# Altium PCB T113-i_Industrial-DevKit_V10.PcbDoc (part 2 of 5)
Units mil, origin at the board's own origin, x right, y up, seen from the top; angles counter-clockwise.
Board outline 4212.61 x 3188.98 mil, 4 copper layers (Top Layer, GND, PWR, Bottom Layer); 249 components, 236 nets, 911 pads, 571 vias.
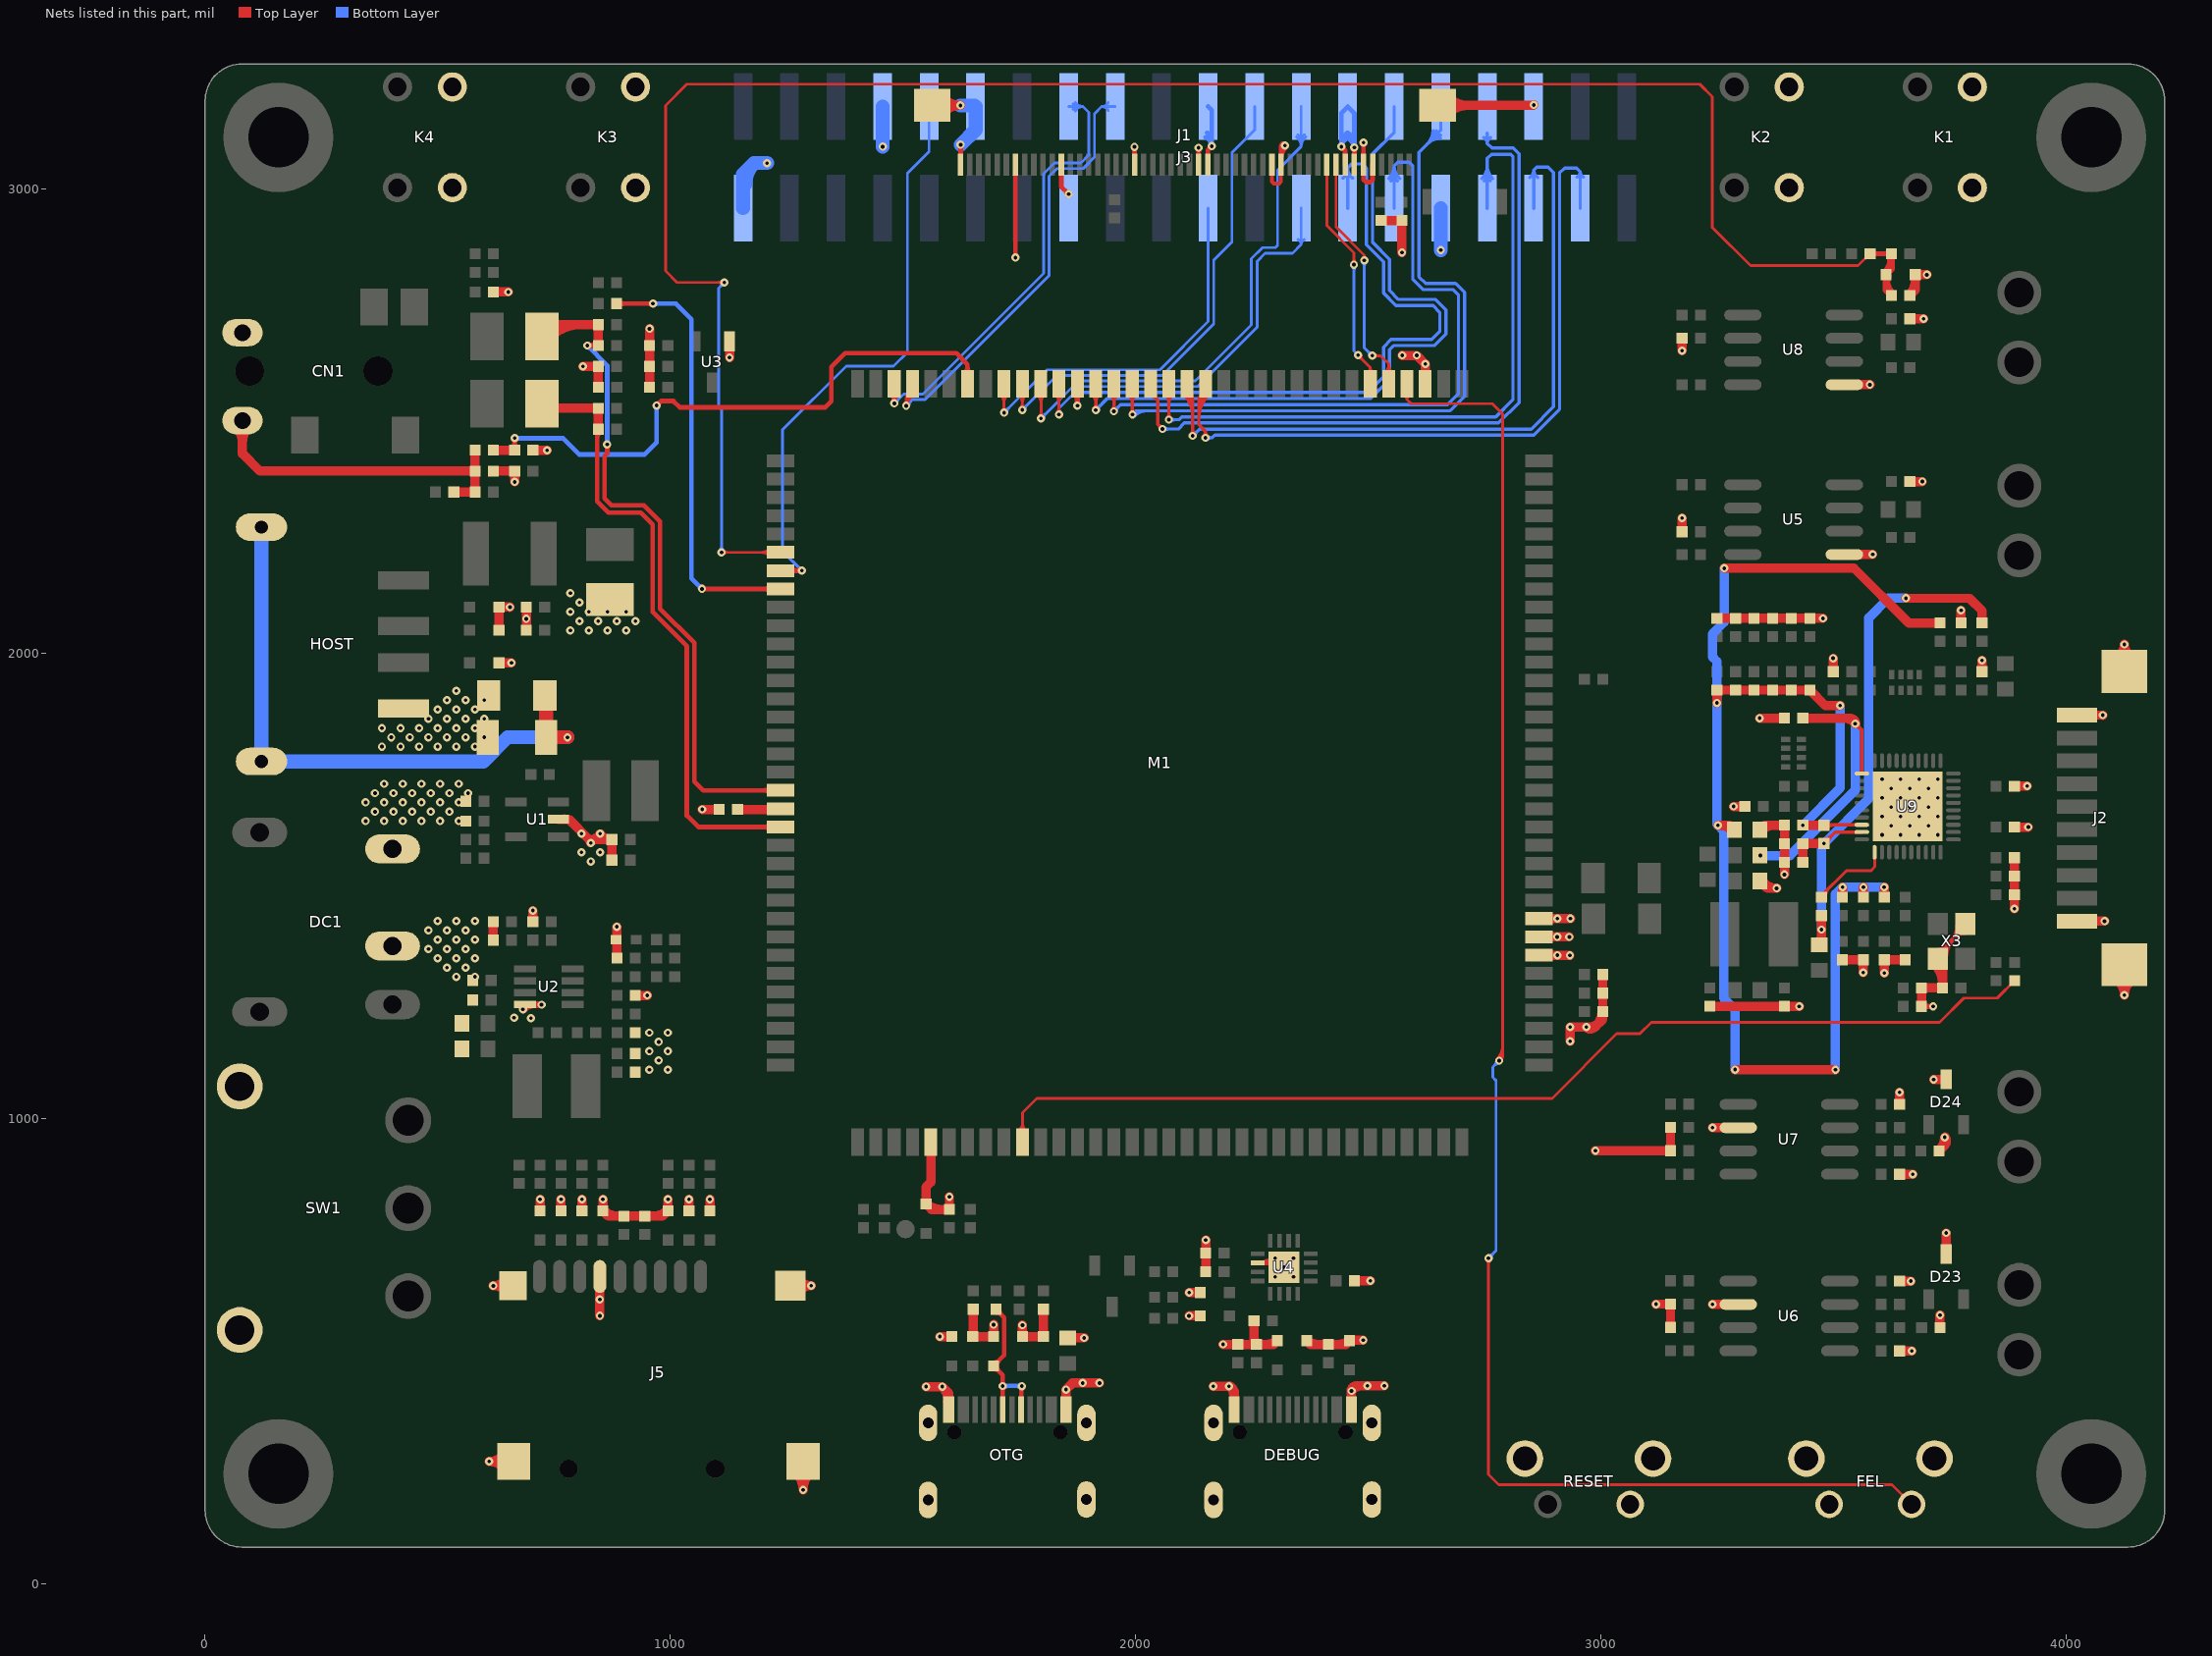
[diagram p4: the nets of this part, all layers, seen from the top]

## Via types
v1: diameter 17.72, hole 7.87, Top Layer to Bottom Layer, tented both sides, 571 vias

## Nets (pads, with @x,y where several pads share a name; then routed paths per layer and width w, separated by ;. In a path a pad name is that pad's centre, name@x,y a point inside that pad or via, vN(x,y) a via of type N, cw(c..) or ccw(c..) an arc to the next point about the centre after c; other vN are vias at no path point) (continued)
DP_P0: D17.2 OTG.A6 OTG.B6 R38.1 | length 487.7
  Top Layer w9.53: D17.2@1695,461.46 cw(c1695,444.45) 1707.03,456.48 cw(c1719.06,468.5) 1702.05,468.5 cw(c1719.06,468.5) 1707.03,480.53 cw(c1695,492.56) D17.2@1695,475.55 ; R38.1@1700,583.27 cw(c1700,566.26) 1712.03,578.29 cw(c1724.06,590.32) R38.1@1707.05,590.32 ; R38.1@1700,590.32 1718,572.32 1718,491.5 D17.2@1695,468.5 1714.72,448.78 v1(1714.72,425.05) OTG.A6@1714.72,374.13 ; v1@1711.83,422.16 cw(c1704.84,415.17) 1714.72,415.17 cw(c1724.61,415.17) v1@1717.62,422.16 ; v1@1711.83,427.95 ccw(c1704.84,434.93) 1714.72,434.93 ccw(c1724.61,434.93) v1@1717.62,427.95 ; OTG.B6@1754.09,374.13 1754.09,423.32 v1(1755.62,424.84) ; 1754.09,411.29 cw(c1769.17,411.29) v1@1758.51,421.95
  Bottom Layer w9.53: v1(1714.72,425.05) 1755.41,425.05 v1(1755.62,424.84) ; v1@1717.62,422.16 cw(c1724.61,415.17) 1724.61,425.05 cw(c1724.61,434.93) v1@1717.62,427.95 ; 1745.23,425.05 cw(c1745.23,414.45) v1@1752.72,421.95 ; 1746.24,425.05 ccw(c1746.24,434.22) v1@1752.72,427.74
DVDD10: C77.1 R94.1 U9.21 | length 701.7
  Top Layer w8: v1@3547.3,1844.51 cw(c3547.3,1832.78) 3555.59,1841.08 cw(c3563.88,1849.37) v1@3552.16,1849.37 ; v1(3547.3,1849.37) 3561.6,1835.07 U9.21@3561.6,1742.16
  Top Layer w20: C77.1@3434.68,1861.26 3435.01,1860.94 3535.73,1860.94 ; 3522.12,1860.94 cw(c3522.12,1824.2) v1@3548.11,1850.18 ; v1(3547.3,1849.37) 3535.73,1860.94 ; v1@3548.43,1849.49 ccw(c3535.73,1848.17) 3535.73,1860.94
  Bottom Layer w20: v1(3343.64,1565.87) 3407.09,1565.87 3547.3,1706.07 v1(3547.3,1849.37)
DVDD33: C64.1 C67.1 R77.1 R84.2 R85.2 R130.2 U9.29 | length 1357.6
  Top Layer w8: R130.2@3477.09,1592.75 cw(c3490.24,1587.45) R130.2@3486.57,1601.15 ; v1(3480,1591.57) 3504.59,1616.16 U9.29@3561.6,1616.16 ; R130.2@3480,1596.43 ccw(c3480,1608.16) 3488.29,1599.87 ccw(c3496.59,1591.57) R130.2@3484.86,1591.57 ; R130.2@3480,1599.39 ccw(c3480,1618.24) 3493.33,1604.91 ccw(c3506.67,1591.57) R130.2@3487.81,1591.57 ; R130.2@3481.17,1588.66 ccw(c3475.87,1601.81) R130.2@3489.57,1598.14
  Top Layer w20: C67.1@3434.68,1551.26 C64.1@3434.68,1591.26 3435,1591.57 v1(3480,1591.57) ; R77.1@3467.9,1377.88 ccw(c3450.77,1395.01) 3475,1395.01 ; R77.1@3470,1373.82 3475,1378.82 R85.2@3475,1436.57 ; v1(3656.12,2119.13) 3656.35,2118.9 3793.43,2118.9 3820,2092.32 R84.2@3820,2065.94
  Bottom Layer w20: v1(3475.02,1406.53) 3475.02,1586.59 v1(3480,1591.57) 3576.39,1687.97 3576.39,2076.97 3618.55,2119.13 v1(3656.12,2119.13) ; 3475.02,1582.31 cw(c3489.27,1582.31) v1@3479.19,1592.38
DVDDRG: C63.1 C66.1 R87.2 R90.1 R91.1 R92.1 R101.1 R102.1 R103.1 R104.1 R105.1 R106.1 R130.1 U9.28 | length 3216.2
  Top Layer w8: R130.1@3480,1630.94 3480.92,1631.86 U9.28@3561.6,1631.86 ; R130.1@3485.52,1625.42 cw(c3501.07,1609.87) 3501.07,1631.86 ; R130.1@3485.52,1636.47 ccw(c3496.64,1647.59) 3496.64,1631.86
  Top Layer w20: v1(3250.16,1893.93) 3250,1894.09 R105.1@3250,1921.57 R104.1@3290,1921.57 R90.1@3330,1921.57 R91.1@3370,1921.57 R92.1@3410,1921.57 R106.1@3450,1921.57 3483.14,1888.43 v1(3515.22,1888.43) ; v1(3252.23,1630.7) 3278,1630.7 C66.1@3287.44,1621.26 ; v1@3255.53,1630.7 cw(c3255.53,1591.31) C66.1@3283.38,1619.16 ; v1@3265.74,2183.73 3544.55,2183.73 3662.34,2065.94 R87.2@3730,2065.94 ; v1(3289,1105.62) v1@3504.92,1105.62 ; v1(3435,1630.94) R130.1@3480,1630.94 ; R103.1@3520,1475.94 3520,1497.78 v1(3520.28,1498.06) ; R102.1@3565,1475.94 3565,1497.91 v1(3565.15,1498.06) ; v1(3609.56,1498.06) 3609.56,1476.38 R101.1@3610,1475.94
  Bottom Layer w20: v1(3265.74,2183.5) 3265.74,2067.58 3241,2042.84 3241,1992.36 3250.16,1983.2 v1(3250.16,1893.93) 3250.16,1632.76 v1(3252.23,1630.7) 3264.37,1618.56 3264.37,1259.11 3288.65,1234.83 3288.65,1105.96 v1(3289,1105.62) ; v1(3435,1630.94) 3515.45,1711.4 3515.45,1888.2 v1(3515.22,1888.43) ; v1(3504.92,1105.45) 3504.92,1482.7 v1(3520.28,1498.06) v1(3565.15,1498.06) v1(3609.56,1498.06)
EPHY_CLK_25M: M1.44 R80.2 | length 2354.2
  Top Layer w6: M1.44@1749.27,973.37 ccw(c1730.87,991.77) 1756.89,991.77 ccw(c1782.91,991.77) M1.44@1764.51,973.37 ; M1.44@1756.89,950 1756.89,1012.56 1788.12,1043.79 2895.67,1043.79 3034.54,1182.66 3084.25,1182.66 3108.84,1207.25 3728.9,1207.25 3780.99,1259.34 3852.77,1259.34 R80.2@3890,1296.57
FEL: FEL.1 M1.106 | length 3640.2
  Top Layer w6: M1.106@2578.51,2554.7 cw(c2573.8,2546.04) 2583.66,2546.04 ; M1.106@2583.66,2579.92 2583.66,2546.04 ; M1.106@2588.81,2554.7 ccw(c2593.52,2546.04) 2583.66,2546.04 ; v1@2754.85,695.75 cw(c2745.19,686.09) 2758.85,686.09 ; 2758.85,685.41 cw(c2773.47,685.41) v1@2763.13,695.75 ; v1(2758.99,699.89) 2758.85,699.75 2758.85,235.23 2781,213.07 3626.29,213.07 FEL.1@3668.58,170.78 ; v1@2777.76,1128.89 ccw(c2749.5,1157.14) 2789.46,1157.14 ; v1(2781.9,1124.75) 2789.46,1132.31 ; v1@2782,1124.65 ccw(c2763.99,1142.66) 2789.46,1142.66 ; v1@2783.16,1130.47 ccw(c2784.63,1137.13) 2789.46,1132.31 ; v1@2787.62,1126.01 cw(c2794.28,1127.48) 2789.46,1132.31 ; 2583.66,2546.04 2592.48,2537.22 2767.47,2537.22 2789.46,2515.23 2789.46,1132.31
  Bottom Layer w6: v1(2758.99,699.89) 2775.1,716.01 2775.1,1082.16 2768.15,1089.11 2768.15,1111 v1(2781.9,1124.75) ; v1@2758.99,705.75 ccw(c2758.99,719.9) 2768.99,709.9 ccw(c2778.99,699.89) v1@2764.85,699.89 ; v1@2776.04,1124.75 cw(c2761.9,1124.75) 2771.9,1114.75 cw(c2781.9,1104.75) v1@2781.9,1118.89
FMINL: J3.24 M1.133 | length 1170.7
  Top Layer w6: v1@1503.07,2536.91 ccw(c1493.07,2546.91) 1507.22,2546.91 ; v1@1504.29,2537.84 ccw(c1499.73,2545.72) 1508.53,2543.37 ; v1@1505.55,2538.38 ccw(c1503.31,2545.96) 1510.94,2543.91 ccw(c1520.69,2541.3) v1@1512.16,2535.9 ; v1@1507.22,2530.01 cw(c1532.64,2530.01) M1.133@1524.23,2554 ; v1(1507.22,2532.76) 1507.22,2549.58 ; v1@1507.21,2538.46 cw(c1529.68,2538.46) M1.133@1522.25,2559.66 ; 1509.56,2547.23 ccw(c1521.44,2544.04) v1@1511.81,2536.4 ; M1.133@1510.29,2561.28 cw(c1498.74,2558.06) 1507.22,2549.58 ; v1@1511.36,2536.91 cw(c1521.36,2546.91) 1507.21,2546.91 ; M1.133@1519.09,2553.51 ccw(c1517.05,2539.75) 1507.22,2549.58 ; M1.133@1520.27,2565.33 ccw(c1526.71,2546.92) 1507.22,2546.92 ; M1.133@1520.67,2579.92 1520.67,2563.04 1507.22,2549.58
  Bottom Layer w6: v1(1507.22,2532.76) 1520.59,2546.14 1547.63,2546.14 1814.37,2812.88 1814.37,3026.27 1831.15,3043.06 1887.54,3043.06 1911.83,3067.36 1911.83,3160.84 1927.25,3176.26 ; v1@1507.22,2538.62 ccw(c1507.22,2552.77) 1517.22,2542.76 ccw(c1527.22,2532.76) v1@1513.07,2532.76 ; J3.24@1941.38,3167.95 ccw(c1927.25,3160.09) 1927.25,3176.26 ; J3.24@1941.38,3184.56 cw(c1927.25,3192.43) 1927.25,3176.26 ; J3.24@1956.3,3176.26 1927.25,3176.26
FMINR: J3.26 M1.134 | length 1143.8
  Top Layer w6: M1.134@1473.68,2556.55 cw(c1455.62,2538.5) v1@1481.15,2538.5 ; v1@1476.49,2540.95 ccw(c1465.06,2547.56) M1.134@1477.81,2550.97 ; v1@1477.42,2542.17 ccw(c1468.42,2551.17) M1.134@1481.15,2551.17 ; M1.134@1477.61,2551.72 ccw(c1490.92,2555.29) v1@1484.36,2543.17 ; v1@1478.78,2543.18 ccw(c1473.18,2553.54) 1484.55,2550.49 ccw(c1494.68,2547.78) v1@1486.27,2541.52 ; v1@1481.15,2532.12 1481.15,2579.78 M1.134@1481.3,2579.92 ; v1@1481.15,2537.8 cw(c1507.67,2537.8) M1.134@1488.92,2556.55 ; M1.134@1481.15,2553.16 ccw(c1496.7,2553.16) v1@1485.71,2542.17
  Bottom Layer w6: v1(1481.57,2538.02) 1501.68,2558.14 1542.66,2558.14 1802.3,2817.79 1802.3,3031.62 1825.74,3055.06 1882.57,3055.06 1899.83,3072.33 1899.83,3163.73 1887.31,3176.26 ; v1@1481.57,2543.88 ccw(c1481.57,2558.03) 1491.57,2548.02 ccw(c1501.57,2538.02) v1@1487.42,2538.02 ; J3.26@1856.3,3176.26 1887.31,3176.26 ; J3.26@1865.66,3170.34 cw(c1876.41,3163.54) 1876.41,3176.26 cw(c1876.41,3188.98) J3.26@1865.66,3182.18 ; J3.26@1870.73,3167.13 cw(c1887.31,3156.65) 1887.31,3176.26 ; J3.26@1870.73,3185.39 ccw(c1887.31,3195.87) 1887.31,3176.26
GND: C1.1 C2.1 C3.1 C4.2 C5.2 C7.2 C8.2 C9.2 C10.1 C11.1 C12.2 C13.2 C15.2 C16.2 C18.2 C19.2 C20.2 C21.1 C23.2 C24.2 C25.2 C30.1 C33.1 C34.2 C35.2 C36.2 C37.2 C38.1 C39.1 C40.1 C41.2 C42.1 C43.2 C44.1 C45.2 C46.2 C47.2 C48.2 C49.1 C50.1 C51.1 C52.2 C53.2 C54.1 C55.1 C56.1 C57.1 C58.2 C59.1 C60.2 C61.2 C62.2 C63.2 C64.2 C65.2 C66.2 C67.2 C68.2 C69.2 C70.2 C71.2 C72.2 C73.2 C74.2 C75.2 C76.2 C77.2 CN1.2 D2.1 D3.1 D4.1 D5.1 D6.1 D7.1 D8.1 D9.1 D10.1 D11.1 D12.1 D13.2 D14.2 D15.1 D16.1 D17.1 D18.1 D19.1 D20.1 D21.1 D22.1 D23.3 D24.3 D25.1 DC1.2 DC1.3 DEBUG.A1B12 DEBUG.B1A12 DEBUG.SHELL FEL.2 FEL.3 FEL.4 HOST.4 J1.5 J1.6 J1.7 J1.8 J1.15 J1.16 J1.23 J1.24 J1.31 J1.39 J1.44 J1.50 J1.51 J1.52 J2.1 J2.10 J2.11 J2.12 J3.6 J3.9 J3.14 J3.20 J3.25 J3.30 J3.34 J3.39 J5.6 J5.10 J5.11 J5.12 J5.13 K1.3 K1.4 K2.3 K2.4 K3.3 K3.4 K4.3 K4.4 LED1.2 M1.39 M1.75 M1.76 M1.77 M1.105 OTG.A1B12 OTG.B1A12 OTG.SHELL R2.2 R4.2 R6.2 R10.2 R17.2 R18.2 R22.1 R27.2 R28.2 R40.1 R41.1 R42.1 R49.1 R50.1 R53.2 R62.2 R79.2 R81.2 R82.2 R83.2 R86.2 R95.2 R96.2 R97.2 R98.2 R99.2 R100.2 RESET.1 RESET.3 RESET.4 SW1.4 SW1.5 U1.2 U2.4 U3.1 U4.2 U4.17 U5.5 U6.2 U7.2 U8.5 U9.41 X3.2 X3.4 | length 10123.8
  Top Layer w8: J1.16@2293.3,3051.03 2293.3,3014.92 2297.46,3010.76 2309.39,3010.76 2312.99,3014.36 J1.15@2312.99,3051.03
  Top Layer w10: v1@1621.39,3091.52 cw(c1615.07,3085.19) 1624.01,3085.19 ; J1.50@1624.01,3051.03 1624.01,3094.14 v1(1624.12,3094.25) ; 1624.01,3084.67 cw(c1633.7,3084.67) v1@1626.85,3091.52 ; v1@1739.41,2854.19 ccw(c1732.86,2860.73) 1742.12,2860.73 ; v1@1742.12,2851.47 J1.44@1742.12,3051.03 ; 1742.12,2860.81 ccw(c1751.49,2860.81) v1@1744.87,2854.19 ; J1.39@1840.55,3051.03 1840.55,3003.89 v1(1856.48,2987.96) ; v1@1852.63,2987.96 ccw(c1843.31,2987.96) 1849.9,2994.55 ccw(c1856.48,3001.13) v1@1856.48,2991.82 ; v1@1995.23,3087.01 cw(c1988.45,3080.23) 1998.03,3080.23 ; v1(1997.95,3089.74) 1998.03,3089.66 J1.31@1998.03,3051.03 ; 1998.03,3080.62 cw(c2007.07,3080.62) v1@2000.68,3087.01 ; v1@2133.04,3085.12 cw(c2126.32,3078.4) 2135.82,3078.4 ; v1(2135.77,3087.85) 2135.82,3087.79 J1.24@2135.82,3051.03 ; 2135.82,3078.67 cw(c2144.95,3078.67) v1@2138.5,3085.12 ; J1.23@2155.51,3051.03 2155.51,3082.71 v1(2163.85,3091.05) ; v1@2159.99,3091.05 cw(c2150.68,3091.05) 2157.27,3084.46 cw(c2163.85,3077.88) v1@2163.85,3087.19 ; U4.2@2262.35,690.1 2309.63,690.1 v1(2319.43,680.3) ; U4.2@2266.78,690.1 ccw(c2266.78,733.22) U4.17@2297.27,702.73 ; U4.17@2290.92,690.1 ccw(c2290.92,709.08) U4.17@2304.34,695.66 ; J1.15@2312.99,3051.03 2312.99,3084.27 v1(2321.08,3092.36) ; J1.15@2312.99,3063.52 cw(c2349.92,3063.52) v1@2323.81,3089.63 ; 2312.99,3087.67 cw(c2325.78,3087.67) v1@2316.74,3096.7 ; U4.17@2315.57,680.3 ccw(c2306.26,680.3) 2312.85,686.89 ccw(c2319.43,693.47) U4.17@2319.43,684.16 ; v1@2317.22,3092.36 cw(c2307.91,3092.36) 2314.49,3085.77 cw(c2321.08,3079.19) v1@2321.08,3088.5 ; v1@2442.66,3086.24 cw(c2442.66,3076.93) 2449.25,3083.51 cw(c2455.84,3090.1) v1@2446.52,3090.1 ; v1(2442.66,3090.1) 2450.78,3081.98 J1.8@2450.78,3051.03 ; v1@2467.77,3085.35 cw(c2461.24,3078.82) 2470.47,3078.82 ; J1.7@2470.47,3051.03 v1@2470.47,3088.05 ; 2470.47,3078.7 cw(c2479.87,3078.7) v1@2473.23,3085.35 ; v1@2487.45,3096.02 cw(c2480.92,3089.49) 2490.15,3089.49 ; 2490.15,3089.38 cw(c2499.55,3089.38) v1@2492.91,3096.02 ; v1@2490.15,3098.73 J1.6@2490.15,3051.03 2490.15,3019.13 2495.37,3013.91 2504.99,3013.91 2509.84,3018.77 J1.5@2509.84,3051.03 ; C60.2@3689.69,1241.26 v1(3715,1241.24) ; C60.2@3694.5,1236.44 cw(c3706.08,1224.87) 3706.08,1241.24 ; C60.2@3694.5,1246.08 ccw(c3706.18,1257.75) v1@3706.18,1241.24 ; 3701.74,1242.43 ccw(c3705.16,1255.19) v1@3712.78,1244.39 ; v1@3712.27,1238.51 ccw(c3705.69,1231.92) 3705.69,1241.24 ccw(c3705.69,1250.55) v1@3712.27,1243.97 ; X3.2@3725.47,1343.86 3725.47,1353.24 3784.53,1412.3 X3.4@3784.53,1418.66 ; X3.2@3725.47,1362.48 ccw(c3725.47,1384.79) 3741.24,1369.02 ; X3.2@3732.12,1345.83 cw(c3766.08,1345.83) 3742.07,1369.84 ; X3.2@3742.12,1345.83 cw(c3800.23,1345.83) 3759.14,1386.91 ; 3753,1380.77 ccw(c3717.07,1416.69) X3.4@3767.88,1416.69 ; 3763.59,1391.37 cw(c3784.53,1370.43) X3.4@3784.53,1400.04 ; X3.4@3770.07,1397.84 ccw(c3751.22,1416.69) X3.4@3777.88,1416.69 ; U4.17@2303.86,700 ccw(c2313.82,700) 2306.78,692.96 cw(c2313.82,700) U4.17@2303.86,700
  Top Layer w15: v1@683.96,1234.04 cw(c711.22,1206.78) U2.4@711.22,1245.33 ; U2.4@687.9,1245.33 722.85,1245.33 v1(723.11,1245.07)
  Top Layer w20: v1(610.31,262.77) v1@610.49,262.95 ; v1(619.31,640.52) v1@619.69,640.9 ; C12.2@619.39,1383.72 R6.2@619.39,1423.72 ; C24.2@619.69,2392.48 C21.1@665.32,2392.48 665.32,2369.3 v1(665.19,2369.18) ; R22.1@619.68,2777.52 v1(651.48,2777.52) ; D20.1@631.5,1980 658.37,1980 v1(658.41,1979.95) ; D19.1@631.5,2050 D21.1@631.5,2100 655.08,2100 v1(655.22,2099.87) ; J5.12@643.61,247.05 ccw(c610.49,220.51) v1@610.49,262.95 ; J5.12@643.61,278.85 cw(c610.49,305.39) v1@610.49,262.95 ; J5.10@646.52,628.37 ccw(c619.69,605.92) v1@619.69,640.9 ; J5.10@646.52,653.43 cw(c619.69,675.88) v1@619.69,640.9 ; J5.10@661.5,640.9 v1@619.69,640.9 ; J5.12@663.46,262.95 v1@610.49,262.95 ; C42.1@690.32,2050 v1(690.31,2074.74) C43.2@690.31,2100 ; C8.2@704.39,1423.72 v1(704.39,1447.57) ; C25.2@704.69,2437.48 734.83,2437.48 v1(735.04,2437.28) ; D4.1@720.04,802.09 v1(720.02,826.43) ; U1.2@759.08,1643.76 781.99,1643.76 v1@825.75,1600 ; D9.1@765.04,802.09 v1(765.02,826.43) ; U1.2@772.21,1644.11 cw(c772.21,1621.35) 788.3,1637.44 ; D10.1@810.04,802.09 v1(810.02,826.43) ; v1(811.91,2617.58) 812.01,2617.48 R18.2@845.31,2617.48 845.31,2572.8 R17.2@845.63,2572.48 ; v1@828.19,1593.81 cw(c843.14,1578.86) 843.14,1600 ; v1@848.12,1612.27 ccw(c874.31,1634.09) C10.1@874.32,1600 ; v1(848.47,576.19) 848.36,576.3 v1(848.36,611.14) 848.5,611.28 J5.6@848.5,660.59 ; v1@849.92,1612.33 cw(c825.75,1629.87) v1@825.75,1600 ; v1(855.02,826.43) D12.1@855.04,802.09 866.85,790.28 C35.2@900.04,790.28 C37.2@945.04,790.28 983.23,790.28 D11.1@995.04,802.09 v1(995.02,826.43) ; D12.1@856.32,803.37 ccw(c887.93,834.97) 887.93,790.28 ; C11.1@874.32,1556 C10.1@874.32,1600 ; v1(885.09,1412.73) 885.31,1412.51 R10.2@885.31,1345 ; R4.2@924.69,1265 950.17,1265 v1(950.38,1265.21) ; C13.2@955.31,2572.52 C16.2@955.31,2617.52 C15.2@955.31,2662.52 v1(955.34,2698.5) ; 962.15,790.28 ccw(c962.15,834.97) D11.1@993.76,803.37 ; D6.1@1040.04,802.09 v1(1040.02,826.43) ; v1(1068.74,1665.11) 1068.85,1665 C30.1@1105.28,1665 ; D8.1@1085.04,802.09 v1(1085.02,826.43) ; v1(1127.28,2636.67) 1127.4,2636.8 U3.1@1127.4,2671.81 ; J5.11@1257.95,640.9 v1@1302.91,640.9 ; J5.13@1268.51,240.11 cw(c1234.14,201.92) v1@1285.52,201.92 ; J5.11@1275.93,627.41 cw(c1302.91,607.18) v1@1302.91,640.9 ; J5.11@1275.93,654.39 ccw(c1302.91,674.62) v1@1302.91,640.9 ; v1(1285.47,201.87) v1@1285.52,201.91 ; J5.13@1285.52,262.95 v1@1285.52,201.91 ; J5.13@1302.53,240.11 ccw(c1336.89,201.92) v1@1285.52,201.92 ; v1(1303.01,641) v1@1302.91,640.9 ; v1@1549.95,423.92 v1(1550.06,423.8) v1(1584.66,423.8) ; D25.1@1551.28,817.78 ccw(c1582.89,849.38) 1582.89,804.69 ; M1.39@1560.04,950 1560.04,863.41 1550,853.37 D25.1@1550,816.5 1561.81,804.69 C58.2@1600,804.69 1600,832.07 v1(1599.94,832.13) ; J1.52@1562.99,3178.97 v1@1623.29,3178.97 ; v1(1579.45,531.51) D15.1@1605,531.5 ; J1.52@1586,3162.15 cw(c1623.28,3129.26) v1@1623.28,3178.97 ; J1.52@1586,3195.8 ccw(c1623.28,3228.69) v1@1623.28,3178.97 ; OTG.A1B12@1596.78,390.82 ccw(c1555.09,394.22) v1(1584.66,423.8) ; OTG.A1B12@1598.58,374.13 1598.58,409.88 v1(1584.66,423.8) ; v1(1623.53,3178.73) v1@1623.29,3178.97 ; R40.1@1651,590.32 1651,532.5 D18.1@1650,531.5 D17.1@1695,531.5 v1(1695,557) ; v1(1757,556) D16.1@1757,531.5 D22.1@1802,531.5 R41.1@1802,590.32 ; OTG.B1A12@1850.55,374.13 1850.55,417.39 v1(1850.68,417.52) 1864.66,431.5 v1(1886.46,431.5) v1(1922.72,431.5) v1@1922.84,431.38 ; C40.1@1854.41,528.78 1889.55,528.78 v1(1889.78,528.55) ; v1(2115.15,576.06) 2115.31,576.22 D14.2@2139.17,576.22 ; v1(2115.39,626.18) v1(2115.39,626.18) D13.2@2139.17,626.22 ; C36.2@2150.98,671.22 C38.1@2150.98,711.22 v1(2151.05,738.75) v1(2151.05,738.75) ; v1(2167.41,424.63) v1(2201.06,424.63) 2212.21,413.48 DEBUG.A1B12@2212.21,374.13 ; v1(2188.4,514.73) v1(2188.4,514.73) C34.2@2220,514.69 R28.2@2260,514.69 ; v1@2201.54,425.66 cw(c2193.64,408.86) 2212.21,408.86 ; v1@2201.87,425.44 cw(c2176.89,400.46) DEBUG.A1B12@2212.21,400.46 ; 2254.75,531.74 ccw(c2277.05,531.74) R28.2@2261.28,515.97 ; C39.1@2254.75,565.3 2254.75,519.94 R28.2@2260,514.69 ; 2281.24,514.69 ccw(c2281.24,546.48) D7.1@2303.72,524 ; D7.1@2305,522.72 2296.97,514.69 R28.2@2260,514.69 ; D5.1@2368,522.72 2376.03,514.69 R27.2@2415,514.69 2451.97,514.69 D3.1@2460,522.72 2461.24,523.95 v1(2489.58,523.95) ; D5.1@2369.28,524 ccw(c2391.76,546.48) 2391.76,514.69 ; 2436.24,514.69 ccw(c2436.24,546.48) D3.1@2458.72,524 ; v1@2463.33,414.68 cw(c2475.6,413.35) 2475.6,425.7 ; v1@2463.66,415.37 cw(c2488.6,390.43) 2488.6,425.7 ; DEBUG.B1A12@2464.18,374.13 2464.18,414.28 v1(2464.47,414.56) 2475.6,425.7 ; C33.1@2470.35,651.22 2504.92,651.22 v1(2505,651.3) ; C1.1@2528.02,2931.24 C2.1@2573.02,2931.24 v1(2572.99,2862.71) ; v1(2534.97,425.7) v1(2498.83,425.7) 2475.6,425.7 ; v1@2573.71,2641.37 v1(2573.83,2641.25) v1(2604.64,2641.25) v1(2623.01,2622.89) M1.105@2623.03,2579.92 ; J1.51@2649.6,3178.97 2855.38,3178.97 v1(2856.2,3179.8) ; J1.51@2671.53,3160.99 cw(c2714.94,3117.57) 2714.94,3178.97 cw(c2714.94,3240.38) J1.51@2671.53,3196.96 ; M1.75@2867.13,1351.57 2906.93,1351.57 v1(2907.03,1351.47) 2933.81,1351.47 v1(2933.93,1351.35) ; M1.76@2867.13,1390.94 v1@2906.66,1390.94 ; M1.77@2867.13,1430.32 2907.08,1430.32 v1(2907.15,1430.39) v1(2934.99,1430.39) v1@2935.11,1430.51 ; v1(2906.68,1390.93) 2932.63,1390.93 v1(2932.74,1390.81) ; v1@2934.88,1166.39 v1(2934.64,1166.63) 2934.64,1197.08 v1(2934.76,1197.2) v1(2969.36,1197.2) 2988.19,1197.2 ; v1@2968.63,1196.32 ccw(c2977.93,1207.46) 2988.19,1197.2 ; v1@2969.36,1196.06 ccw(c2969.36,1238.75) 2999.55,1208.56 ; v1@2988.79,931.26 C46.2@3150.31,931.26 C48.2@3150.31,981.26 ; 2990.06,1199.08 ccw(c2959.14,1230) C55.1@3002.87,1230 ; C57.1@3004.68,1310 C56.1@3004.68,1270 C55.1@3004.68,1230 3004.68,1213.7 2988.19,1197.2 ; v1(3119.15,601.13) 3119.28,601.26 C45.2@3150.31,601.26 C47.2@3150.31,551.26 ; v1(3175.18,2291.23) 3175.32,2291.09 C49.1@3175.32,2262 ; C54.1@3175.32,2678.15 3175.32,2651.54 v1(3175.41,2651.44) ; C73.2@3235,1241.57 C69.2@3395,1241.57 3426.92,1241.57 v1(3427.02,1241.47) ; v1@3240.6,600.63 U6.2@3295.85,600.63 ; v1(3240.8,980.49) 3240.94,980.63 U7.2@3295.85,980.63 ; R99.2@3250,2075.94 R98.2@3290,2075.94 R81.2@3330,2075.94 R82.2@3370,2075.94 R83.2@3410,2075.94 R100.2@3450,2075.94 3477.54,2075.94 v1(3477.77,2075.71) ; v1(3285.9,1671.36) 3286.01,1671.26 C62.2@3310.31,1671.26 ; v1@3342.05,1861.26 C77.2@3395.31,1861.26 ; C71.2@3342.56,1503.54 cw(c3342.56,1484.91) C71.2@3355.73,1498.09 ; C71.2@3342.56,1511.26 3358.51,1495.31 v1(3378.46,1495.31) cw(c3378.46,1532.08) C71.2@3347.41,1512.37 ; C66.2@3342.56,1621.26 3352.56,1631.26 C63.2@3395.31,1631.26 C64.2@3395.31,1591.26 C67.2@3395.31,1551.26 3395.31,1524.99 v1(3395.18,1524.86) ; C66.2@3346.62,1619.16 cw(c3375.83,1589.96) 3375.83,1631.26 ; v1(3499.88,1990.03) 3500,1989.91 C59.1@3500,1960.94 ; R97.2@3520,1341.57 R96.2@3565,1341.57 3565,1314.49 v1(3564.78,1314.27) ; U5.5@3524.15,2213.15 v1(3584.92,2213.14) ; U8.5@3524.15,2578.15 3578.81,2578.15 v1(3578.88,2578.22) ; v1(3609.92,1313.32) 3610,1313.39 R95.2@3610,1341.57 C61.2@3655,1341.57 ; v1(3642.59,1056.78) 3642.76,1056.61 R50.1@3642.76,1030.63 ; C50.1@3642.76,500.63 3668.92,500.63 v1(3669.05,500.5) ; R49.1@3642.76,650.63 v1(3666.74,650.64) ; C51.1@3642.76,880.63 3671,880.63 v1(3671.12,880.51) ; C23.2@3663.4,2771.28 ccw(c3631.8,2802.89) 3676.5,2802.89 ; R53.2@3664.69,2370 v1@3691.66,2370 ; R62.2@3664.69,2720 3694.34,2720 v1(3694.41,2719.93) ; C23.2@3664.69,2770 3676.5,2781.81 D2.1@3676.5,2815 3701.01,2815 v1(3701.4,2814.61) ; C60.2@3689.69,1241.26 R79.2@3689.69,1281.26 C72.2@3735.31,1281.26 3735.31,1334.01 X3.2@3725.47,1343.86 ; v1(3716.03,1084.2) 3716.08,1084.26 D24.3@3743.07,1084.26 ; X3.2@3717.23,1333.65 cw(c3673.57,1289.99) C72.2@3735.31,1289.99 ; C53.2@3726.58,932.01 ccw(c3702.92,959.91) v1(3739.51,959.92) C53.2@3739.51,942.38 ; C53.2@3727.76,930.63 C53.2@3739.51,942.38 ; C53.2@3729.06,931.93 ccw(c3701.08,959.92) v1@3740.65,959.92 ; C52.2@3729.69,550.63 3729.69,577.7 v1(3729.77,577.79) ; v1@3740.39,960.64 cw(c3729.89,952) C53.2@3739.51,942.38 ; D23.3@3743.07,708.63 v1(3743.07,754.26) ; v1(3774.9,2092.78) 3775,2092.68 C70.2@3775,2065.94 ; C68.2@3820,1960.94 3820,1985.51 v1(3820.13,1985.64) ; v1(3889.68,1451.24) C74.2@3889.69,1481.26 R86.2@3889.69,1521.26 C65.2@3889.69,1561.26 ; C76.2@3889.69,1627 3919.46,1627 v1(3919.54,1627.08) ; C75.2@3889.69,1715 v1(3916.93,1715) ; J2.1@4023.82,1424.8 4083.32,1424.8 v1(4083.42,1424.7) ; J2.10@4023.82,1867.71 4079.66,1867.71 v1(4079.74,1867.62) ; J2.12@4107.15,1300.23 cw(c4086.14,1266.15) v1@4126.18,1266.15 ; J2.11@4110.13,1993.94 ccw(c4097.39,2019.75) v1(4126.19,2019.76) ; v1(4125.95,1265.92) v1@4126.18,1266.15 ; J2.12@4126.18,1331.1 v1@4126.18,1266.15 ; J2.11@4126.18,1961.42 v1(4126.19,2019.76) ; J2.11@4142.23,1993.94 cw(c4154.97,2019.75) v1(4126.19,2019.76) ; J2.12@4145.21,1300.23 ccw(c4166.22,1266.15) v1@4126.18,1266.15 ; v1@825.75,1600 C10.1@874.32,1600
  Bottom Layer w10: J3.20@2150.37,3110.62 cw(c2141.65,3090.21) v1@2163.85,3090.21 ; J3.20@2154.3,3119.82 cw(c2148.12,3105.35) J3.20@2163.85,3105.35 ; J3.20@2156.3,3176.26 2163.85,3168.71 v1(2163.85,3091.05) ; 2161.09,3100.5 ccw(c2170.81,3103.1) v1@2165.78,3094.39 ; v1@2161.12,3093.78 ccw(c2154.54,3100.36) 2163.85,3100.36 ccw(c2173.17,3100.36) v1@2166.58,3093.78 ; v1@2439.93,3092.83 ccw(c2433.35,3099.41) 2442.66,3099.41 ccw(c2451.98,3099.41) v1@2445.39,3092.83 ; v1@2440.81,3093.48 ccw(c2435.6,3102.98) 2446.06,3100.18 ; v1@2442.66,3087.5 cw(c2465.77,3087.5) J3.14@2460.04,3109.88 ; v1(2442.66,3090.1) 2442.66,3162.62 J3.14@2456.3,3176.26 2470.5,3162.06 v1(2470.5,3088.08) ; 2442.66,3100.38 cw(c2462.47,3100.38) J3.14@2457.56,3119.57 ; J3.14@2452.06,3110.02 cw(c2444.86,3085.41) v1@2470.5,3085.41 ; J3.14@2454.87,3119.61 cw(c2448.76,3098.76) 2470.5,3098.76 ; 2466.99,3098.51 ccw(c2478.26,3101.53) v1@2472.43,3091.42 ; v1@2467.77,3090.81 ccw(c2461.18,3097.39) 2470.5,3097.39 ccw(c2479.81,3097.39) v1@2473.23,3090.81
  Bottom Layer w30: J3.39@1156.3,2957.75 1156.3,3030.73 1180.31,3054.74 v1(1207.8,3054.74) ; J3.39@1161.38,3009.52 cw(c1224.85,3009.52) 1179.97,3054.4 ; J3.34@1456.3,3176.26 1456.3,3090.26 v1(1456.58,3089.98) ; v1(1623.53,3178.73) 1653.83,3178.73 J3.30@1656.3,3176.26 1656.3,3126.42 v1(1624.12,3094.25) ; J3.9@2656.3,2957.75 2656.3,2867.81 v1(2656.42,2867.69)
  other v1: 3240.57,600.6 2300,660 2340,660 2300,700 2340,700 2988.77,931.28 955,1105 995,1105 975,1125 955,1145 995,1145 975,1165 955,1185 995,1185 700,1216 664,1217 683,1235 540,1305 580,1305 520,1325 560,1325 500,1345 540,1345 580,1345 480,1365 520,1365 560,1365 500,1385 540,1385 580,1385 480,1405 520,1405 560,1405 500,1425 540,1425 580,1425 829,1553 809,1573 849,1573 829,1593 3605,1610 3645,1610 3685,1610 3725,1610 809,1613 849,1613 3625,1630 3665,1630 3705,1630 345,1640 385,1640 425,1640 465,1640 505,1640 545,1640 3605,1650 3645,1650 3685,1650 3725,1650 365,1660 405,1660 445,1660 485,1660 525,1660 3625,1670 3665,1670 3705,1670 345,1680 385,1680 425,1680 465,1680 505,1680 545,1680 3605,1690 3645,1690 3685,1690 3725,1690 365,1700 405,1700 445,1700 485,1700 525,1700 565,1700 3625,1710 3665,1710 3705,1710 385,1720 425,1720 465,1720 505,1720 545,1720 3605,1730 3645,1730 3685,1730 3725,1730 380,1800 420,1800 460,1800 500,1800 540,1800 580,1800 400,1820 440,1820 480,1820 520,1820 560,1820 600,1820 380,1840 420,1840 460,1840 500,1840 540,1840 580,1840 480,1860 520,1860 560,1860 600,1860 3342.03,1861.28 500,1880 540,1880 580,1880 520,1900 560,1900 600,1900 540,1920 785,2050 825,2050 865,2050 905,2050 805,2070 845,2070 885,2070 925,2070 785,2090 825,2090 865,2090 905,2090 805,2110 785,2130 3691.68,2370.03 1742.14,2851.46 2490.18,3098.75
GNDE: C44.2 HOST.5 HOST.6 R42.2 | length 1457
  Top Layer w30: R42.2@723.17,1895.45 cw(c699.44,1871.72) 732.99,1871.72 ; R42.2@730.24,1910 732.99,1907.24 C44.2@732.99,1820 v1(778.9,1820)
  Bottom Layer w30: HOST.5@110.64,1778.31 ccw(c85.84,1803.11) 120.91,1803.11 ccw(c155.98,1803.11) HOST.5@131.18,1778.31 ; HOST.6@110.64,2261.69 cw(c85.84,2236.89) 120.91,2236.89 cw(c155.98,2236.89) HOST.6@131.18,2261.69 ; HOST.6@120.91,2271.96 HOST.5@120.91,1768.04 598.04,1768.04 650,1820 v1(778.9,1820)
GPADC0: C23.1 D2.2 M1.6 R13.1 R14.2 | length 4585.1
  Top Layer w6: v1(1110.08,2217.76) v1(1110.08,2217.76) M1.6@1237.2,2217.72 ; v1@1112.02,2794.02 ccw(c1102.02,2784.02) 1102.02,2798.16 ccw(c1102.02,2812.3) v1@1112.02,2802.3 ; v1@1114.22,2213.62 cw(c1124.12,2203.72) 1124.12,2217.72 ; v1@1114.22,2221.9 ccw(c1124.33,2232.01) 1124.33,2217.72 ; v1(1116.16,2798.16) 1014.22,2798.16 989.79,2822.58 989.79,3178.75 1035.54,3224.5 3213.26,3224.5 3240.31,3197.45 3240.31,2916.14 3322.1,2834.36 3553.73,2834.36 R14.2@3579.37,2860 ; M1.6@1213.83,2210.09 ccw(c1195.43,2191.69) 1195.43,2217.72 ccw(c1195.43,2243.74) M1.6@1213.83,2225.34
  Top Layer w10: R14.2@3579.37,2860 R13.1@3625.32,2860 ; R14.2@3584.19,2855.18 cw(c3595.81,2843.56) 3595.81,2860 cw(c3595.81,2876.44) R14.2@3584.19,2864.82 ; R13.1@3620.5,2855.18 ccw(c3608.87,2843.56) 3608.87,2860 ccw(c3608.87,2876.44) R13.1@3620.5,2864.82
  Top Layer w15: D2.2@3610.46,2818.05 ccw(c3574.58,2853.92) R13.1@3625.32,2853.92 ; D2.2@3613.5,2808.92 ccw(c3664.24,2808.92) C23.1@3628.36,2773.05 ; 3615.66,2800.87 cw(c3630.9,2804.96) D2.2@3617.24,2812.84 ; R13.1@3621.58,2857.84 cw(c3607.92,2849.96) 3623.16,2845.87 ; C23.1@3625.32,2770 3613.5,2781.81 D2.2@3613.5,2815 3625.32,2826.81 R13.1@3625.32,2860
  Bottom Layer w6: v1@1105.94,2221.9 ccw(c1095.94,2231.9) 1110.08,2231.9 ccw(c1124.22,2231.9) v1@1114.22,2221.9 ; v1(1110.08,2217.76) 1110.08,2523.93 1103.78,2530.24 1103.78,2785.78 v1(1116.16,2798.16) ; v1@1110.3,2798.16 cw(c1096.16,2798.16) 1106.16,2788.16 cw(c1116.16,2778.16) v1@1116.16,2792.3
GPADC1: J3.32 M1.7 | length 1377.9
  Top Layer w6: M1.7@1237.2,2178.35 1282.6,2178.35 v1(1282.71,2178.46) ; M1.7@1260.57,2170.72 cw(c1278.98,2152.32) 1278.98,2178.35 cw(c1278.98,2204.37) M1.7@1260.57,2185.97 ; 1267.4,2175.24 cw(c1271.46,2160.09) v1@1279.65,2173.47 ; 1267.77,2181.35 ccw(c1271.45,2195.09) v1@1279.43,2183.31 ; 1268.29,2178.35 ccw(c1268.29,2192.88) v1@1278.57,2182.6 ; 1268.85,2178.35 cw(c1268.85,2164.6) v1@1278.57,2174.32 ; 1270.83,2176.16 ccw(c1267.92,2187) v1@1277.64,2181.39 ; 1271.29,2180.41 cw(c1268.58,2170.3) v1@1277.64,2175.53
  Bottom Layer w6: v1@1276.85,2178.46 ccw(c1262.71,2178.46) 1272.71,2188.46 ccw(c1282.71,2198.46) v1@1282.71,2184.32 ; v1(1282.71,2178.46) 1241.35,2219.82 1241.35,2481.31 1378.18,2618.14 1480.01,2618.14 1509.74,2647.87 1509.74,3032.51 1556.3,3079.08 J3.32@1556.3,3176.26
HBIAS: C25.1 M1.130 R15.2 | length 1419.8
  Top Layer w10: C25.1@660.5,2442.3 ccw(c648.92,2453.88) 665.3,2453.88 ; v1@662.57,2460.49 cw(c655.98,2453.9) 665.3,2453.9 cw(c674.61,2453.9) v1@668.03,2460.49 ; C25.1@665.32,2437.48 v1(665.3,2463.22) ; 665.3,2453.97 ccw(c681.8,2453.97) C25.1@670.13,2442.3 ; v1(970.34,2533.56) 979.73,2542.94 1006.78,2542.94 1020.07,2529.65 1333.11,2529.65 1346.4,2542.95 1346.4,2616.26 1375.95,2645.81 1614.9,2645.81 1638.78,2621.93 M1.130@1638.78,2579.92 ; v1@970.34,2537.41 ccw(c970.34,2546.73) 976.93,2540.14 ccw(c983.52,2533.56) v1@974.2,2533.56 ; M1.130@1632.57,2601.88 ccw(c1617.58,2616.87) 1638.78,2616.87 ccw(c1659.97,2616.87) M1.130@1644.99,2601.88
  Top Layer w20: R15.2@619.69,2437.48 C25.1@665.32,2437.48
  Bottom Layer w10: v1(665.3,2463.22) 769.32,2463.22 804.17,2428.37 945.22,2428.37 970.34,2453.49 v1(970.34,2533.56) ; v1@668.03,2460.49 cw(c674.61,2453.9) 674.61,2463.22 cw(c674.61,2472.53) v1@668.03,2465.94 ; v1@967.62,2530.83 cw(c961.03,2524.24) 970.34,2524.24 cw(c979.66,2524.24) v1@973.07,2530.83
HCEC: J3.18 M1.127 | length 1133.2
  Top Layer w6: M1.127@1749.27,2556.55 cw(c1731.31,2538.59) 1756.71,2538.59 ; v1@1752.56,2528.19 ccw(c1742.56,2538.19) 1756.71,2538.19 ccw(c1770.85,2538.19) v1@1760.85,2528.19 ; v1(1756.71,2524.05) 1756.71,2579.74 M1.127@1756.89,2579.92 ; 1756.71,2537.71 cw(c1783.35,2537.71) M1.127@1764.51,2556.55
  Bottom Layer w6: v1(1756.71,2524.05) 1830.92,2598.26 2057.61,2598.26 2168.3,2708.95 2168.3,2845.97 2207.33,2885 2207.33,3077.33 2256.3,3126.3 J3.18@2256.3,3176.26 ; v1@1756.71,2529.91 ccw(c1756.71,2544.05) 1766.71,2534.05 ccw(c1776.71,2524.05) v1@1762.57,2524.05
HHPD: J3.19 M1.128 | length 911.2
  Top Layer w6: M1.128@1709.9,2556.55 cw(c1691.74,2538.4) 1717.42,2538.4 ; v1@1713.27,2522.12 ccw(c1703.27,2532.12) 1717.42,2532.12 ccw(c1731.56,2532.12) v1@1721.56,2522.12 ; v1(1717.42,2517.98) 1717.42,2579.82 M1.128@1717.52,2579.92 ; 1717.42,2537.9 cw(c1743.79,2537.9) M1.128@1725.14,2556.55
  Bottom Layer w6: v1(1717.42,2517.98) 1809.7,2610.26 2052.64,2610.26 2156.3,2713.92 J3.19@2156.3,2957.75 ; v1@1717.42,2523.84 ccw(c1717.42,2537.98) 1727.42,2527.98 ccw(c1737.42,2517.98) v1@1723.28,2517.98
HP_DET: M1.8 R21.2 | length 1044
  Top Layer w10: R21.2@884.69,2752.48 v1(962.67,2752.48) ; R21.2@889.5,2747.66 cw(c901.13,2736.04) 901.13,2752.48 cw(c901.13,2768.92) R21.2@889.5,2757.3 ; v1@959.94,2749.75 ccw(c953.36,2743.17) 953.36,2752.48 ccw(c953.36,2761.79) v1@959.94,2755.21 ; v1(1068.03,2139.2) 1068.25,2138.98 M1.8@1237.2,2138.98 ; v1@1070.76,2141.92 ccw(c1077.88,2149.04) 1077.88,2138.98 ; M1.8@1215.25,2132.77 ccw(c1200.26,2117.78) 1200.26,2138.98 ccw(c1200.26,2160.17) M1.8@1215.25,2145.18
  Bottom Layer w10: v1(962.67,2752.48) 1012.01,2752.48 1045.49,2719.01 1045.49,2161.74 v1(1068.03,2139.2) ; v1@965.4,2749.75 cw(c971.98,2743.17) 971.98,2752.48 cw(c971.98,2761.79) v1@965.4,2755.21 ; v1@1064.17,2139.2 ccw(c1054.86,2139.2) 1061.45,2145.78 ccw(c1068.03,2152.37) v1@1068.03,2143.05
HPOUTFB: C30.2 M1.20 | length 93.2
  Top Layer w20: C30.2@1144.65,1665 1235.67,1665 M1.20@1237.2,1666.54
HPOUTL: C26.2 C29.1 C32.1 M1.19 | length 1742.9
  Top Layer w10: v1(821.54,2662.53) 821.59,2662.48 C29.1@845.32,2662.48 ; v1@823.72,2659.35 cw(c830.77,2649.08) C29.1@833.99,2661.11 ; v1@823.8,2665.66 ccw(c830.76,2675.31) C29.1@833.84,2663.81 ; v1@824.27,2659.8 cw(c830.74,2653.33) 830.74,2662.48 ; v1@824.27,2665.26 ccw(c830.97,2671.95) 830.97,2662.48 ; C29.1@840.5,2657.66 ccw(c828.87,2646.04) 828.87,2662.48 ccw(c828.87,2678.92) C29.1@840.5,2667.3 ; v1@861.55,2447.09 cw(c854.96,2440.51) 864.27,2440.51 cw(c873.59,2440.51) v1@867,2447.09 ; v1(864.27,2449.82) 864.27,2429.78 858.51,2424.01 858.51,2333.89 873.54,2318.86 943.46,2318.86 977.75,2284.57 977.75,2096.71 1051.52,2022.94 1051.52,1725.12 1070.74,1705.91 M1.19@1237.2,1705.91 ; M1.19@1215.25,1699.7 ccw(c1200.26,1684.71) 1200.26,1705.91 ccw(c1200.26,1727.1) M1.19@1215.25,1712.11
  Top Layer w20: C32.1@724.1,2682.48 749.1,2707.48 C26.2@845.31,2707.48 C29.1@845.32,2662.48 ; C32.1@727.94,2694.39 cw(c759.55,2662.78) 759.55,2707.48 ; C32.1@742.08,2680.24 cw(c807.84,2614.49) 807.84,2707.48 ; C32.1@742.08,2716.21 ccw(c763.16,2737.29) 763.16,2707.48
  Bottom Layer w10: v1@821.54,2658.67 cw(c821.54,2649.35) 828.13,2655.94 cw(c834.71,2662.53) v1@825.4,2662.53 ; v1(821.54,2662.53) 864.27,2619.79 v1(864.27,2449.82) ; v1@861.55,2452.55 ccw(c854.96,2459.14) 864.27,2459.14 ccw(c873.59,2459.14) v1@867,2452.55
HPOUTR: C27.2 C28.1 C31.1 M1.21 | length 1388.7
  Top Layer w10: 842.51,2459.27 cw(c868.53,2459.27) C27.2@850.13,2477.66 ; C27.2@845.31,2482.48 842.51,2479.68 842.51,2327.26 866.91,2302.86 936.55,2302.86 961.75,2277.66 961.75,2089.57 1035.52,2015.81 1035.52,1651.55 1059.9,1627.17 M1.21@1237.2,1627.17 ; M1.21@1215.25,1620.96 ccw(c1200.26,1605.97) 1200.26,1627.17 ccw(c1200.26,1648.36) M1.21@1215.25,1633.37
  Top Layer w20: C31.1@724.1,2537.48 734.1,2527.48 C28.1@845.32,2527.48 C27.2@845.31,2482.48
HS_MIC: C22.1 C24.1 CN1.1 R15.1 R20.1 | length 796.7
  Top Layer w20: CN1.1@66.15,2487.36 cw(c32.82,2454.03) 79.96,2454.03 cw(c127.1,2454.03) CN1.1@93.77,2487.36 ; CN1.1@79.96,2501.17 79.96,2430.1 117.58,2392.48 C24.1@580.32,2392.48 ; R20.1@534.68,2347.48 C22.1@580.32,2347.48 C24.1@580.32,2392.48 ; R15.1@580.32,2437.48 C24.1@580.32,2392.48
HSCL: J3.16 M1.126 | length 1303.4
  Top Layer w6: M1.126@1788.64,2556.55 cw(c1768.38,2536.3) 1797.03,2536.3 ; v1@1792.88,2509.98 ccw(c1782.88,2519.98) 1797.03,2519.98 ccw(c1811.17,2519.98) v1@1801.17,2509.98 ; M1.126@1796.26,2579.92 1797.03,2579.15 v1(1797.03,2505.84) ; 1797.03,2540 cw(c1820.43,2540) M1.126@1803.88,2556.55
  Bottom Layer w6: v1(1797.03,2505.84) 1877.45,2586.26 2128.75,2586.26 2249.4,2706.91 2249.4,2785.53 ; v1@1797.03,2511.69 ccw(c1797.03,2525.84) 1807.03,2515.84 ccw(c1817.03,2505.84) v1@1802.89,2505.84 ; 2249.37,2785.56 2249.37,2848.9 2273.28,2872.82 2300.46,2872.82 2305.39,2877.74 2305.39,3039.39 2356.3,3090.31 ; J3.16@2346.05,3110.83 cw(c2330.64,3090.31) 2356.3,3090.31 ; J3.16@2349.65,3115.63 cw(c2339.66,3102.32) 2356.3,3102.32 cw(c2372.94,3102.32) J3.16@2362.95,3115.63 ; J3.16@2356.3,3176.26 2356.3,3090.31 ; J3.16@2366.55,3110.83 ccw(c2381.96,3090.31) 2356.3,3090.31
HSDA: J3.15 M1.125 | length 1014.6
  Top Layer w6: M1.125@1828.01,2556.55 cw(c1809.88,2538.43) 1835.52,2538.43 ; v1@1831.37,2518.57 ccw(c1821.37,2528.57) 1835.52,2528.57 ccw(c1849.66,2528.57) v1@1839.66,2518.57 ; v1(1835.52,2514.43) 1835.52,2579.81 M1.125@1835.63,2579.92 ; 1835.52,2537.87 cw(c1861.93,2537.87) M1.125@1843.25,2556.55
  Bottom Layer w6: v1@1831.71,2518.88 ccw(c1824.65,2527.14) 1835.52,2527.14 ; v1(1835.52,2514.43) 1835.52,2527.14 ; v1@1839.32,2518.88 cw(c1846.38,2527.14) 1835.51,2527.14 ; J3.15@2349.4,2890.35 cw(c2344.73,2879.77) 2356.3,2879.77 ; J3.15@2356.3,2957.75 2356.3,2879.77 ; J3.15@2363.19,2890.35 ccw(c2367.86,2879.77) 2356.3,2879.77 ; 1835.52,2527.14 1882.63,2574.26 2133.72,2574.26 2261.4,2701.94 2261.4,2843.52 2278.7,2860.82 2337.34,2860.82 2356.3,2879.77
HTX0N: J3.8 M1.120 | length 1635.4
  Top Layer w7.07: M1.120@2032.48,2553.93 cw(c2032.48,2539.15) 2042.93,2549.6 ; M1.120@2032.48,2579.92 2032.48,2560.05 2048.11,2544.42 ; M1.120@2042.55,2562.31 ccw(c2062.34,2558.65) 2048.11,2544.42 ; v1@2052.75,2482.92 ccw(c2039.89,2482.92) 2048.98,2492.01 ccw(c2058.07,2501.09) v1@2058.07,2488.24 ; v1(2058.07,2482.92) 2048.11,2492.87 2048.11,2544.42
  Bottom Layer w7.07: v1(2058.07,2482.92) 2092.13,2482.92 2105.08,2495.87 2780.55,2495.87 2824.51,2539.83 2824.51,3074.56 2812.15,3086.92 2766.33,3086.92 2756.3,3096.95 ; v1@2061.83,2479.15 cw(c2070.92,2470.07) 2070.92,2482.92 cw(c2070.92,2495.77) v1@2061.83,2486.68 ; J3.8@2748.53,3109.88 cw(c2741.66,3096.95) 2756.3,3096.95 ; J3.8@2756.3,3119.35 2756.3,3096.95 ; J3.8@2764.07,3109.88 ccw(c2770.94,3096.95) 2756.3,3096.95
HTX0P: J3.7 M1.119 | length 1703.5
  Top Layer w7.07: M1.119@2064.61,2556.93 cw(c2047.12,2539.44) 2071.85,2539.44 cw(c2096.58,2539.44) M1.119@2079.09,2556.93 ; v1@2068.06,2506.76 ccw(c2058.91,2515.92) 2071.85,2515.92 ; v1(2071.82,2503) M1.119@2071.85,2579.92 ; 2071.85,2515.79 ccw(c2084.61,2515.79) v1@2075.59,2506.76
  Bottom Layer w7.07: v1(2071.82,2503) 2093.73,2503 2099.67,2508.94 2774.61,2508.94 2811.44,2545.77 2811.44,3069.15 2806.73,3073.85 2765.27,3073.85 2756.3,3064.88 J3.7@2756.3,2957.75 ; v1@2075.59,2499.24 cw(c2084.68,2490.15) 2084.68,2503 cw(c2084.68,2515.85) v1@2075.59,2506.76 ; J3.7@2744.6,3021.22 ccw(c2716.36,3049.46) 2756.3,3049.46 ccw(c2796.24,3049.46) J3.7@2768,3021.22 ; J3.7@2749.6,3016.22 ccw(c2733.43,3032.39) 2756.3,3032.39 ccw(c2779.17,3032.39) J3.7@2763,3016.22
HTX1N: J3.11 M1.122 | length 1698.5
  Top Layer w7.07: M1.122@1946.5,2556.93 cw(c1929.04,2539.47) 1953.73,2539.47 ; v1@1949.84,2524.83 ccw(c1940.45,2534.21) 1953.73,2534.21 ; v1@1953.73,2521.06 M1.122@1953.74,2579.92 ; 1953.73,2533.61 ccw(c1966.16,2533.61) v1@1957.37,2524.83 ; 1953.73,2539.41 cw(c1978.5,2539.41) M1.122@1960.98,2556.93
  Bottom Layer w7.07: v1(1953.6,2521.06) 1967.82,2535.27 2670.67,2535.27 2694.49,2559.09 2694.49,2771.08 2682.77,2782.8 2617.99,2782.8 2596.33,2804.46 2596.33,3048.1 2587.86,3056.58 2563.57,3056.58 2556.3,3049.3 ; v1@1953.6,2526.39 ccw(c1953.6,2539.24) 1962.69,2530.15 ccw(c1971.78,2521.06) v1@1958.93,2521.06 ; J3.11@2544.63,3021.25 ccw(c2516.75,3049.3) 2556.3,3049.3 ; J3.11@2549.62,3016.24 ccw(c2533.65,3032.3) 2556.3,3032.3 ccw(c2578.95,3032.3) J3.11@2562.98,3016.24 ; J3.11@2556.3,2957.75 2556.3,3049.3 ; J3.11@2567.96,3021.25 cw(c2595.85,3049.3) 2556.3,3049.3
HTX1P: J3.10 M1.121 | length 1722.7
  Top Layer w7.07: M1.121@1985.87,2556.93 cw(c1967.77,2538.84) 1993.36,2538.84 ; v1@1989.82,2518.08 ccw(c1981.29,2526.61) 1993.36,2526.61 ; M1.121@1993.11,2579.92 1993.36,2579.67 v1@1993.36,2514.31 ; 1993.36,2527.72 ccw(c2006.99,2527.72) v1@1997.35,2518.08 ; 1993.36,2540.04 cw(c2017.24,2540.04) M1.121@2000.35,2556.93
  Bottom Layer w7.07: v1@1992.35,2515.55 cw(c2008.15,2499.75) 2008.15,2522.09 ; v1(1993.59,2514.31) 2001.37,2522.09 2676.51,2522.09 2707.56,2553.14 2707.56,2776.49 2688.18,2795.87 2623.82,2795.87 2609.62,2810.07 2609.62,3078.11 2656.3,3124.79 J3.10@2656.3,3176.26 ; v1@1997.35,2510.55 cw(c2025.22,2482.68) 2025.22,2522.09 ; 2627.54,3096.03 cw(c2656.3,3067.28) J3.10@2656.3,3107.94 ; 2628.27,3096.76 ccw(c2600.54,3124.49) J3.10@2639.76,3124.49 ; J3.10@2639.61,3108.1 cw(c2656.3,3091.42) J3.10@2656.3,3115.01 ; J3.10@2640.34,3108.83 ccw(c2624.68,3124.49) J3.10@2646.83,3124.49
HTX2N: J3.13 M1.124 | length 1697.8
  Top Layer w7.07: M1.124@1867.76,2556.93 cw(c1850.27,2539.44) 1875,2539.44 cw(c1899.73,2539.44) M1.124@1882.24,2556.93 ; v1@1870.65,2535.76 ccw(c1855.42,2544.56) 1872.41,2549.11 ; v1@1871.5,2536.86 ccw(c1863.04,2545.32) 1875,2545.32 ; 1874.14,2542.63 ccw(c1881.98,2544.73) v1@1877.92,2537.71 ; 1875,2546.58 ccw(c1888.75,2546.58) v1@1879.03,2536.86 ; M1.124@1875,2579.92 1875,2533.36 v1(1875.26,2533.1) ; 1877.46,2548.64 ccw(c1892.05,2544.73) v1@1879.64,2536.13
  Bottom Layer w7.07: v1@1871.5,2536.86 ccw(c1862.41,2545.95) 1875.26,2545.95 ccw(c1888.11,2545.95) v1@1879.03,2536.86 ; v1(1875.26,2533.1) 1875.26,2548.56 1888.43,2561.73 2499.88,2561.73 2533.1,2594.95 2533.1,2658.87 2549.6,2675.37 2637.11,2675.37 2654.28,2692.54 2654.28,2733.87 2639.72,2748.43 2560.03,2748.43 2533.1,2775.37 2533.1,2842.37 2496.21,2879.27 2496.21,3043.53 2486.83,3052.91 2465.06,3052.91 2456.3,3044.15 ; J3.13@2445.91,3022.39 ccw(c2428.34,3044.15) 2456.3,3044.15 ; J3.13@2456.3,2957.75 2456.3,3044.15 ; J3.13@2466.69,3022.39 cw(c2484.26,3044.15) 2456.3,3044.15
HTX2P: J3.12 M1.123 | length 1613.9
  Top Layer w7.07: M1.123@1907.13,2556.93 cw(c1888.09,2537.9) 1915.01,2537.9 ; v1@1910.9,2527.58 ccw(c1900.98,2537.5) 1915.01,2537.5 ; M1.123@1914.37,2579.92 1915.01,2579.28 v1@1915.01,2523.82 ; 1915.01,2535.84 ccw(c1926.69,2535.84) v1@1918.43,2527.58 ; 1915.01,2540.99 cw(c1937.56,2540.99) M1.123@1921.61,2556.93
  Bottom Layer w7.07: v1(1914.67,2523.82) 1939.3,2548.46 2505.39,2548.46 2546.28,2589.34 2546.28,2653.56 2555.01,2662.29 2642.6,2662.29 2667.35,2687.05 2667.35,2739.28 2645.13,2761.5 2565.64,2761.5 2546.28,2780.86 2546.28,2847.68 2509.74,2884.22 2509.74,3074.67 2556.3,3121.24 J3.12@2556.3,3176.26 ; v1@1914.67,2529.14 ccw(c1914.67,2541.99) 1923.75,2532.91 ccw(c1932.84,2523.82) v1@1919.99,2523.82
HTXCN: J3.3 M1.117 | length 1787.2
  Top Layer w7.07: 2136.2,2504.7 cw(c2210.07,2504.7) M1.117@2157.83,2556.93 ; 2136.2,2521.77 cw(c2193,2521.77) M1.117@2152.84,2561.93 ; 2136.2,2538.83 cw(c2175.93,2538.83) M1.117@2147.84,2566.93 ; 2136.75,2548.2 cw(c2150.59,2534.35) M1.117@2150.59,2553.93 ; M1.117@2140.55,2562.13 cw(c2124.91,2558.93) 2136.2,2547.65 ; v1@2146.75,2467.85 ccw(c2137.67,2476.94) 2150.52,2476.94 ccw(c2163.37,2476.94) v1@2154.28,2467.85 ; v1(2150.52,2464.08) 2150.52,2477.73 2136.2,2492.05 2136.2,2547.65 ; M1.117@2150.59,2579.92 2150.59,2562.04 2136.2,2547.65
  Bottom Layer w7.07: v1(2150.52,2464.08) 2165.34,2464.08 2170.89,2469.63 2856.18,2469.63 2911.68,2525.13 2911.68,3033.55 2922.45,3044.32 2947.88,3044.32 2956.3,3035.9 ; v1@2154.28,2460.32 cw(c2163.37,2451.23) 2163.37,2464.08 cw(c2163.37,2476.94) v1@2154.28,2467.85 ; J3.3@2949.1,3024.42 ccw(c2943.55,3035.89) 2956.3,3035.89 ; J3.3@2956.3,2957.75 2956.3,3035.9 ; J3.3@2963.5,3024.42 cw(c2969.05,3035.89) 2956.3,3035.89
HTXCP: J3.5 M1.118 | length 1772.2
  Top Layer w7.07: M1.118@2103.98,2556.93 cw(c2057.74,2510.69) 2123.13,2510.69 ; M1.118@2108.98,2561.93 cw(c2074.81,2527.76) 2123.13,2527.76 ; M1.118@2111.22,2553.93 cw(c2111.22,2539.78) 2121.23,2549.78 ; M1.118@2111.22,2579.92 2111.22,2559.79 2123.13,2547.88 ; M1.118@2113.98,2566.93 cw(c2091.88,2544.83) 2123.13,2544.83 ; v1@2119.36,2471.9 ccw(c2110.28,2480.99) 2123.13,2480.99 ccw(c2135.98,2480.99) v1@2126.89,2471.9 ; M1.118@2120.68,2560.24 ccw(c2131.14,2555.89) 2123.13,2547.88 ; v1@2122.57,2467.58 v1(2123.13,2468.14) 2123.13,2547.88
  Bottom Layer w7.07: v1@2122.57,2467.58 2137.69,2482.7 2850.77,2482.7 2898.61,2530.54 2898.61,3034.58 2886.93,3046.26 2863.05,3046.26 2856.3,3039.51 ; v1@2123.13,2473.46 ccw(c2123.13,2486.31) 2132.22,2477.23 ccw(c2141.3,2468.14) v1@2128.45,2468.14 ; J3.5@2847.48,3023.52 ccw(c2837.4,3039.51) 2856.3,3039.51 ; J3.5@2856.3,2957.75 2856.3,3039.51 ; J3.5@2865.12,3023.52 cw(c2875.2,3039.51) 2856.3,3039.51
INTB: R85.1 U9.31 | length 221.4
  Top Layer w6: R85.1@3475,1475.94 3475,1479.93 3528.6,1533.53 3581.29,1533.53 3589.1,1541.34 U9.31@3589.1,1572.86 ; R85.1@3475,1484.76 ccw(c3475,1496.39) 3483.23,1488.16 ; R85.1@3477.81,1475.94 cw(c3494.23,1475.94) R85.1@3482.62,1487.56 ; R85.1@3483.81,1475.94 cw(c3514.72,1475.94) 3492.86,1497.8
LCD_D2: J1.9 M1.107 | length 662.8
  Top Layer w6: J1.9@2429.05,3031.25 cw(c2424.09,3026.29) 2431.1,3026.29 cw(c2438.12,3026.29) J1.9@2433.16,3031.25 ; J1.9@2431.1,3051.03 2431.1,2917.78 2491.93,2856.95 ; v1@2488.49,2850.21 ccw(c2483.61,2856.95) 2491.93,2856.95 ; v1(2491.93,2845.46) 2491.93,2856.95 ; v1@2495.37,2850.21 cw(c2500.26,2856.95) 2491.93,2856.95 ; v1(2508.93,2640.54) 2526.92,2640.54 2544.29,2623.17 M1.107@2544.29,2579.92 ; v1@2513.08,2636.4 cw(c2523.08,2626.4) 2523.08,2640.54 cw(c2523.08,2654.69) v1@2513.08,2644.69 ; M1.107@2536.67,2603.29 ccw(c2518.27,2621.69) 2544.29,2621.69 ccw(c2570.32,2621.69) M1.107@2551.91,2603.29
  Bottom Layer w6: v1@2487.79,2841.32 cw(c2477.79,2831.32) 2491.93,2831.32 cw(c2506.08,2831.32) v1@2496.08,2841.32 ; v1(2491.93,2845.46) 2491.93,2657.54 v1(2508.93,2640.54) ; v1@2503.07,2640.54 ccw(c2488.93,2640.54) 2498.93,2650.54 ccw(c2508.93,2660.54) v1@2508.93,2646.4
LCD_D3: J1.10 M1.108 | length 595.8
  Top Layer w6: J1.10@2409.36,3031.25 cw(c2404.4,3026.29) 2411.41,3026.29 cw(c2418.43,3026.29) J1.10@2413.47,3031.25 ; J1.10@2411.41,3051.03 2411.41,2920.5 2469.65,2862.26 v1(2469.65,2836.46) ; v1@2465.51,2840.6 ccw(c2455.51,2850.6) 2469.65,2850.6 ccw(c2483.79,2850.6) v1@2473.79,2840.6 ; v1@2478.35,2635.94 cw(c2478.35,2621.8) 2488.35,2631.8 cw(c2498.35,2641.8) v1@2484.21,2641.8 ; v1(2478.35,2641.8) 2504.72,2615.43 ; M1.108@2498.95,2604.64 ccw(c2491.77,2615.43) 2504.72,2615.43 ; M1.108@2504.72,2596.99 2504.72,2615.43 ; M1.108@2510.62,2604.82 cw(c2517.22,2615.43) 2504.72,2615.43
  Bottom Layer w6: v1@2465.51,2832.31 cw(c2455.51,2822.31) 2469.65,2822.31 cw(c2483.79,2822.31) v1@2473.79,2832.31 ; v1(2469.65,2836.46) 2469.65,2650.5 v1(2478.35,2641.8)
